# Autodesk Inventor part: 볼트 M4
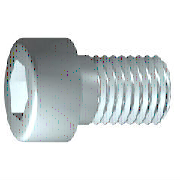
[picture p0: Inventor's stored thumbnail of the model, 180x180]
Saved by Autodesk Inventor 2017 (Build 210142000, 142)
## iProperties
IsCustomPart: 0
Created: 2012-02
Part Number: 볼트 M4
Material: 스테인리스강
Description: 6각 소켓 머리 캡 나사
Document SubType Name: Modeling
Standard: ISO 4762
Designer: mduedu
Standard Revision: Fourth edition 2004-03-01
Standards Organization: ISO
Language: ko-KR
Size Designation: M4 x 12
Categories: <MemberInstance><Categories><Category DisplayName="조임쇠" InternalName="e4da775c-781d-43d5-af7c-5136215cf5a6" Mnemonic="FSTN"><Category DisplayName="볼트" InternalN
Density: 7.75 g/cm^3
Appearance: 반광택
Author: mduedu
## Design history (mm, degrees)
sketch "스케치1"
  geometry: L1 (-1, 0)-(12, 0); L2 (12, 0)-(12, 2); L3 (12, 2)-(1.75, 2); L4 (1.75, 2)-(1.32, 2); L5 (1.32, 2)-(0, 2); L6 (0, 2)-(0, 3.5); L7 (0, 3.5)-(-4, 3.5); L8 (-4, 3.5)-(-4, 1.732); L9 (-4, 1.732)-(-2, 1.732); L10 (-2, 1.732)-(-1, 0); L11 (-7.2, 0)-(15.2, 0) reference; L12 (0, -0.7)-(0, 4.2) reference; L13 (1.75, 2)-(0, 2)
  constraints: 22 end point, 6 parallel, 2 collinear, 2 perpendicular, 1 horizontal, 1 point on line
  dimensions: "d1" = 10.25 distance from line of L3.end L2 (= GEL); "d2" = 0.42952 distance of L4.end L3.end (computed from GAL); "d3" = 4 distance between parallel lines of L8 L6 (= KOH); "d4" = 2 distance of L8.end L9.end (= INTI); "d5" = 60 deg angle of L10 L1; "d6" = 4 diameter of L3 L1 (= GD); "d7" = 4 diameter of L5 L1 (= BDM); "d8" = 3.4641 diameter of L9 L1 (= 1.1547 x SW); "d9" = 7 diameter of L7 L1 (= KOD); "d26" = 12 distance between parallel lines of L12 L2 (= NLG)
revolve "본체" sketch "스케치1" stored, may be unused: angle "d10" = 90 deg
sketch "스케치2"
  geometry: L1 (0, -4.9)-(0, 4.9) reference; L2 (-4.9, 0)-(4.9, 0) reference; L3 (1.732, 0)-(0.866, -1.5); L4 (0.866, -1.5)-(-0.866, -1.5); L5 (-0.866, -1.5)-(-1.732, 0); L6 (-1.732, 0)-(-0.866, 1.5); L7 (-0.866, 1.5)-(0.866, 1.5); L8 (0.866, 1.5)-(1.732, 0); 2 further points
  constraints: 12 end point, 1 coincident, 1 horizontal alignment, 1 point on line, 12 other
extrude "슬롯" join sketch "스케치2" stored distance "d11" = 10; taper "d12" = 0 deg
workplane "Work Plane1"
fillet "Fillet2" dims "d30" = 0.1 (= R)
body "Solid1"
fillet "모깎기1" dims "d17" = 0.4 (= RR)
feature "스레드" dims "d13" = 10.25 (= GEL), "d14" = 0
chamfer "모따기1" distance "d15" = 0.42941 (= -0.5 x SPD + 0.5 x GD); stored, may be unused: second distance "d16" = 0.42941 (= GUL), angle "d27" = 45 deg
other parameters: "GD" = 4 [user parameter; used in 2 equation terms], "NLG" = 12 [user parameter; used in 1 equation term], "GEL" = 10.25 [user parameter; used in 2 equation terms], "KOD" = 7 [user parameter; used in 1 equation term], "KOH" = 4 [user parameter; used in 1 equation term], "INTI" = 2 [user parameter; used in 1 equation term], "GAL" = 0.42941 (= 0.61345 x PTC) [user parameter; used in 1 equation term], "GUL" = 0.42941 (= 0.61345 x PTC) [user parameter; used in 1 equation term], "BDM" = 4 (= NND) [user parameter; used in 1 equation term], "SW" = 3 [user parameter; used in 2 equation terms], "RR" = 0.4 [user parameter; used in 1 equation term], "SPD" = 3.14117 (= NND - 1.2269 x PTC) [user parameter; used in 1 equation term], "d19" = 0, "d28" = 0, "d29" = 0, "R" = 0.1 [user parameter; used in 1 equation term], "TOA" = 30 deg [user parameter], "GD1" = 3.14117 (= THREADDIA - 1.2269 x PTC) [user parameter], "THREADDIA" = 4 [user parameter; used in 1 equation term], "FAWI" = 45 deg [user parameter], "TPU" = 14.28571 (computed from PTC) [user parameter], "PTC" = 0.7 [user parameter; used in 5 equation terms], "NND" = 4 [user parameter; used in 2 equation terms], "E0" = 3.465 (= 1.155 x SW) [user parameter]
